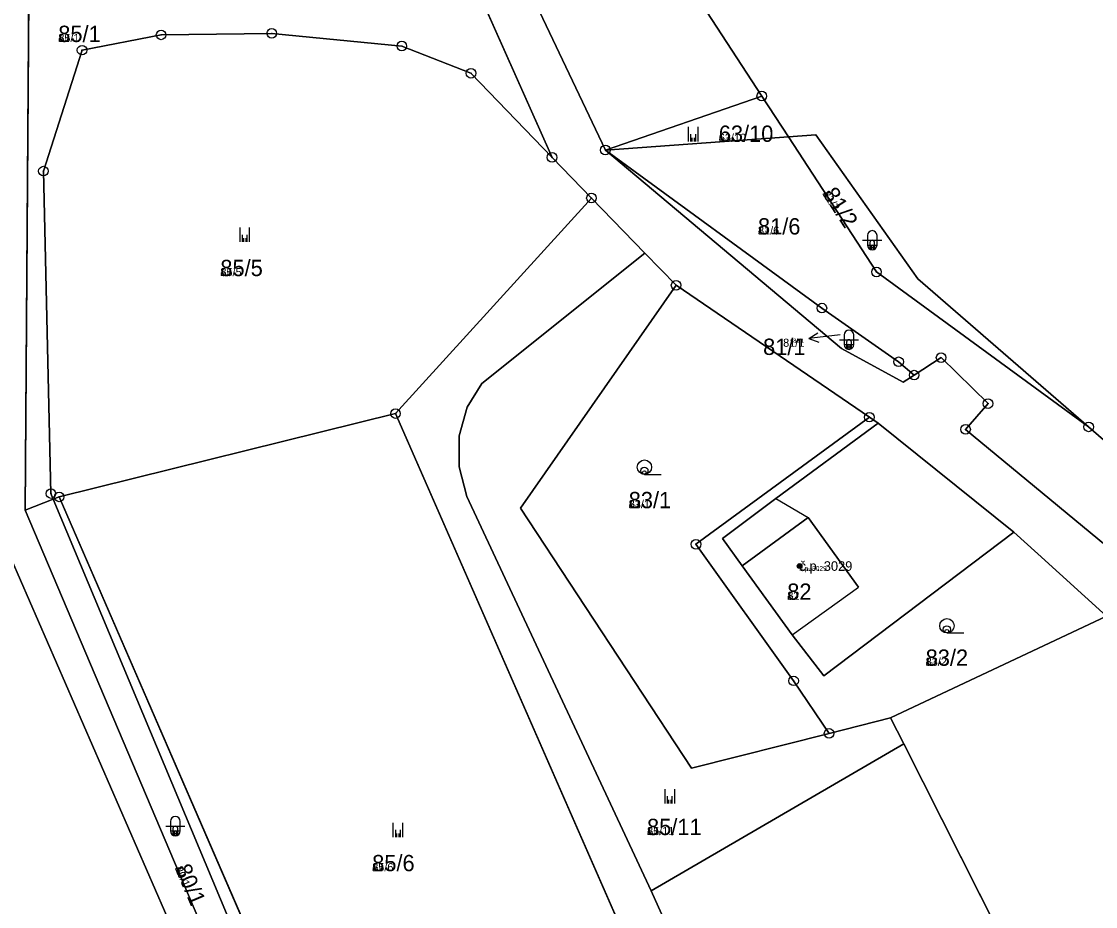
# Model space of a CAD drawing. Extents: x -759873 to -758487, y -975024 to -973516.
# Drawn here: x -759629.6 to -759517.7, y -974197.9 to -974105.6 of the extents above; entities that cross this region are included whole.
import ezdxf

# ---------------------------------------------------------------- set-up
doc = ezdxf.new("R2010")
doc.units = 0
for name, color, linetype in [('KAT_02_hranice parcel', 7, 'Continuous'), ('KAT_03_1000_st čísla parcelní', 7, 'Continuous'), ('KAT_03_1000_čísla parcelní', 7, 'Continuous'), ('KAT_03_1000_čísla popisná', 7, 'Continuous'), ('KAT_03_250_st čísla parcelní', 7, 'Continuous'), ('KAT_03_250_čísla parcelní', 7, 'Continuous'), ('KAT_03_250_čísla popisná', 7, 'Continuous'), ('KAT_03_500_st čísla parcelní', 7, 'Continuous'), ('KAT_03_500_čísla parcelní', 7, 'Continuous'), ('KAT_03_500_čísla popisná', 7, 'Continuous'), ('KAT_04_vnitřní kresba', 7, 'Continuous'), ('KAT_05_1000_značky kultur', 7, 'Continuous'), ('KAT_05_250_značky kultur', 7, 'Continuous'), ('KAT_05_500_značky kultur', 7, 'Continuous'), ('KAT_07_1000_značky budov', 7, 'Continuous'), ('KAT_07_250_značky budov', 7, 'Continuous'), ('KAT_07_500_značky budov', 7, 'Continuous'), ('KAT_11_značky bodu BP', 7, 'Continuous'), ('KAT_12_pomocná šipka', 7, 'Continuous'), ('KAT_14_plocha_budovy', 7, 'Continuous'), ('KAT_14_plocha_pozemek', 7, 'Continuous')]:
    doc.layers.add(name, color=color, linetype=linetype)

msp = doc.modelspace()

# ---------------------------------------------------------------- linework, layer by layer
at = {"layer": 'KAT_02_hranice parcel'}
for p, q in [((-759552.46, -974113.37), (-759576.5, -974076.47)), ((-759585.13, -974095.53), (-759574.33, -974119.77)), ((-759628.88, -974102.32), (-759629.25, -974156.54)), ((-759568.77, -974119), (-759552.46, -974113.37)), ((-759552.46, -974113.37), (-759549.68, -974117.63)), ((-759568.77, -974119), (-759549.68, -974117.63)), ((-759574.33, -974119.77), (-759570.22, -974124.01)), ((-759590.65, -974146.48), (-759570.22, -974124.01)), ((-759570.22, -974124.01), (-759564.64, -974129.76)), ((-759564.64, -974129.76), (-759561.39, -974133.11)), ((-759561.39, -974133.11), (-759541.24, -974146.86)), ((-759625.72, -974155.17), (-759590.65, -974146.48)), ((-759557.68, -974221.71), (-759590.65, -974146.48)), ((-759541.24, -974146.86), (-759540.34, -974147.48)), ((-759540.34, -974147.48), (-759526.16, -974158.85)), ((-759518.38, -974147.87), (-759504.51, -974159.89)), ((-759626.33, -974155.41), (-759629.25, -974156.54)), ((-759625.72, -974155.17), (-759626.33, -974155.41)), ((-759593.05, -974235), (-759626.33, -974155.41)), ((-759591.32, -974234.37), (-759625.72, -974155.17)), ((-759629.25, -974156.54), (-759595.6, -974235.94)), ((-759516.52, -974167.59), (-759539.03, -974178.21)), ((-759539.03, -974178.21), (-759545.44, -974179.83)), ((-759539.03, -974178.21), (-759537.66, -974180.93)), ((-759537.66, -974180.93), (-759563.99, -974196.25)), ((-759537.66, -974180.93), (-759523.59, -974208.74))]:
    msp.add_line(p, q, dxfattribs=at)
for points in [[(-759587.88, -974071.09), (-759581.81, -974091.52), (-759568.77, -974119)], [(-759626.33, -974155.41), (-759626.58, -974154.82), (-759627.36, -974121.2), (-759623.33, -974108.59), (-759615.09, -974107), (-759603.55, -974106.84), (-759589.99, -974108.16), (-759582.78, -974111), (-759574.33, -974119.77)], [(-759632.14, -974110.51), (-759632.59, -974157.4), (-759597.84, -974237.11), (-759593.26, -974247.61)], [(-759549.68, -974117.63), (-759546.81, -974117.43), (-759536.2, -974132.42), (-759518.38, -974147.87)], [(-759549.68, -974117.63), (-759540.5, -974131.72), (-759518.38, -974147.87)], [(-759536.57, -974142.47), (-759537.72, -974143.21), (-759544.16, -974139.71), (-759568.77, -974119)], [(-759536.57, -974142.47), (-759538.19, -974141.08), (-759546.19, -974135.48), (-759568.77, -974119)], [(-759564.64, -974129.76), (-759581.65, -974143.36), (-759583.16, -974145.82), (-759584.02, -974148.81), (-759584.01, -974152.02), (-759583.21, -974155.14), (-759563.99, -974196.25)], [(-759545.44, -974179.83), (-759559.78, -974183.44), (-759577.62, -974156.33), (-759561.39, -974133.11)], [(-759511.82, -974164.15), (-759531.21, -974148.13), (-759528.87, -974145.44), (-759533.76, -974140.65), (-759536.57, -974142.47)], [(-759545.44, -974179.83), (-759549.14, -974174.35), (-759559.32, -974160.11), (-759541.24, -974146.86)], [(-759540.34, -974147.48), (-759550.98, -974155.34), (-759556.57, -974159.52), (-759554.52, -974162.35), (-759549.3, -974169.56), (-759546, -974173.82), (-759526.16, -974158.85)], [(-759526.16, -974158.85), (-759523.66, -974161.11), (-759516.52, -974167.59)], [(-759563.99, -974196.25), (-759561.02, -974202.81), (-759558.92, -974201.9), (-759551.51, -974216.06)]]:
    msp.add_lwpolyline(points, dxfattribs=at)
at = {"layer": 'KAT_03_1000_čísla popisná'}
msp.add_circle((-759548.52, -974162.38), 0.25, dxfattribs=at)
at = {"layer": 'KAT_03_250_čísla popisná'}
msp.add_circle((-759548.52, -974162.38), 0.0625, dxfattribs=at)
at = {"layer": 'KAT_03_500_čísla popisná'}
msp.add_circle((-759548.52, -974162.38), 0.125, dxfattribs=at)
at = {"layer": 'KAT_04_vnitřní kresba'}
for p, q in [((-759550.98, -974155.34), (-759547.61, -974157.31)), ((-759554.52, -974162.35), (-759547.61, -974157.31)), ((-759547.61, -974157.31), (-759542.38, -974164.58)), ((-759549.3, -974169.56), (-759542.38, -974164.58))]:
    msp.add_line(p, q, dxfattribs=at)
at = {"layer": 'KAT_05_1000_značky kultur'}
for p, q in [((-759560.09, -974118.1), (-759560.09, -974116.6)), ((-759559.09, -974118.1), (-759559.09, -974116.6)), ((-759606.86, -974128.58), (-759606.86, -974127.08)), ((-759605.86, -974128.58), (-759605.86, -974127.08)), ((-759541.94, -974128.41), (-759539.94, -974128.41)), ((-759541.44, -974127.91), (-759541.44, -974128.91)), ((-759540.44, -974128.91), (-759540.44, -974127.91)), ((-759544.37, -974138.78), (-759542.37, -974138.78)), ((-759543.87, -974138.28), (-759543.87, -974139.28)), ((-759542.87, -974139.28), (-759542.87, -974138.28)), ((-759564.69, -974152.82), (-759562.94, -974152.82)), ((-759533.15, -974169.36), (-759531.4, -974169.36)), ((-759562.54, -974187.13), (-759562.54, -974185.63)), ((-759561.54, -974187.13), (-759561.54, -974185.63)), ((-759614.11, -974189), (-759614.11, -974190)), ((-759613.11, -974190), (-759613.11, -974189)), ((-759590.88, -974190.64), (-759590.88, -974189.14)), ((-759589.88, -974190.64), (-759589.88, -974189.14)), ((-759614.61, -974189.5), (-759612.61, -974189.5))]:
    msp.add_line(p, q, dxfattribs=at)
for centre in [(-759564.69, -974152.07), (-759533.15, -974168.61)]:
    msp.add_circle(centre, 0.75, dxfattribs=at)
for centre, start, end in [((-759540.94, -974127.91), 0, 180), ((-759540.94, -974128.91), 180, 359.9879), ((-759543.37, -974138.28), 0, 180), ((-759543.37, -974139.28), 180, 359.9879), ((-759613.61, -974189), 0, 180), ((-759613.61, -974190), 180, 359.9879)]:
    msp.add_arc(centre, 0.5, start, end, dxfattribs=at)
at = {"layer": 'KAT_05_250_značky kultur'}
for p, q in [((-759559.71, -974118.1), (-759559.71, -974117.72)), ((-759559.46, -974118.1), (-759559.46, -974117.72)), ((-759606.48, -974128.58), (-759606.48, -974128.21)), ((-759606.23, -974128.58), (-759606.23, -974128.21)), ((-759541.19, -974129.16), (-759540.69, -974129.16)), ((-759541.07, -974129.04), (-759541.07, -974129.29)), ((-759540.81, -974129.29), (-759540.81, -974129.04)), ((-759543.62, -974139.53), (-759543.12, -974139.53)), ((-759543.5, -974139.41), (-759543.5, -974139.66)), ((-759543.24, -974139.66), (-759543.24, -974139.41)), ((-759564.7, -974152.82), (-759564.26, -974152.82)), ((-759533.16, -974169.36), (-759532.72, -974169.36)), ((-759562.16, -974187.13), (-759562.16, -974186.76)), ((-759561.91, -974187.13), (-759561.91, -974186.76)), ((-759613.86, -974190.25), (-759613.36, -974190.25)), ((-759613.74, -974190.13), (-759613.74, -974190.38)), ((-759613.48, -974190.38), (-759613.48, -974190.13)), ((-759590.5, -974190.64), (-759590.5, -974190.27)), ((-759590.25, -974190.64), (-759590.25, -974190.27))]:
    msp.add_line(p, q, dxfattribs=at)
for centre in [(-759564.7, -974152.63), (-759533.16, -974169.17)]:
    msp.add_circle(centre, 0.187, dxfattribs=at)
for centre, start, end in [((-759540.94, -974129.04), 0, 180), ((-759540.94, -974129.29), 180, 359.9879), ((-759543.37, -974139.41), 0, 180), ((-759543.37, -974139.66), 180, 359.9879), ((-759613.61, -974190.13), 0, 180), ((-759613.61, -974190.38), 180, 359.9879)]:
    msp.add_arc(centre, 0.125, start, end, dxfattribs=at)
at = {"layer": 'KAT_05_500_značky kultur'}
for p, q in [((-759559.84, -974118.1), (-759559.84, -974117.35)), ((-759559.33, -974118.1), (-759559.33, -974117.35)), ((-759606.61, -974128.58), (-759606.61, -974127.83)), ((-759606.1, -974128.58), (-759606.1, -974127.83)), ((-759541.19, -974128.66), (-759541.19, -974129.16)), ((-759540.69, -974129.16), (-759540.69, -974128.66)), ((-759541.44, -974128.91), (-759540.44, -974128.91)), ((-759543.87, -974139.28), (-759542.87, -974139.28)), ((-759543.62, -974139.03), (-759543.62, -974139.53)), ((-759543.12, -974139.53), (-759543.12, -974139.03)), ((-759564.7, -974152.82), (-759563.82, -974152.82)), ((-759533.16, -974169.36), (-759532.28, -974169.36)), ((-759562.29, -974187.13), (-759562.29, -974186.38)), ((-759561.79, -974187.13), (-759561.79, -974186.38)), ((-759614.11, -974190), (-759613.11, -974190)), ((-759613.86, -974189.75), (-759613.86, -974190.25)), ((-759613.36, -974190.25), (-759613.36, -974189.75)), ((-759590.63, -974190.64), (-759590.63, -974189.89)), ((-759590.12, -974190.64), (-759590.12, -974189.89))]:
    msp.add_line(p, q, dxfattribs=at)
for centre in [(-759564.7, -974152.44), (-759533.16, -974168.98)]:
    msp.add_circle(centre, 0.375, dxfattribs=at)
for centre, start, end in [((-759540.94, -974128.66), 0, 180), ((-759540.94, -974129.16), 180, 359.9879), ((-759543.37, -974139.03), 0, 180), ((-759543.37, -974139.53), 180, 359.9879), ((-759613.61, -974189.75), 0, 180), ((-759613.61, -974190.25), 180, 359.9879)]:
    msp.add_arc(centre, 0.25, start, end, dxfattribs=at)
at = {"layer": 'KAT_07_1000_značky budov'}
msp.add_circle((-759548.53, -974162.38), 0.175, dxfattribs=at)
at = {"layer": 'KAT_07_250_značky budov'}
msp.add_circle((-759548.52, -974162.38), 0.0437, dxfattribs=at)
at = {"layer": 'KAT_07_500_značky budov'}
msp.add_circle((-759548.52, -974162.38), 0.0875, dxfattribs=at)
at = {"layer": 'KAT_11_značky bodu BP'}
for centre, radius in [((-759603.55, -974106.84), 0.5), ((-759615.09, -974107), 0.5), ((-759615.09, -974107), 0.0303), ((-759603.55, -974106.84), 0.0303), ((-759623.33, -974108.59), 0.5), ((-759623.33, -974108.59), 0.0303), ((-759589.99, -974108.16), 0.5), ((-759589.99, -974108.16), 0.0303), ((-759582.78, -974111), 0.5), ((-759582.78, -974111), 0.0303), ((-759552.46, -974113.37), 0.5), ((-759552.46, -974113.37), 0.0303), ((-759568.77, -974119), 0.5), ((-759574.33, -974119.77), 0.5), ((-759574.33, -974119.77), 0.0303), ((-759568.77, -974119), 0.0303), ((-759627.36, -974121.2), 0.5), ((-759627.36, -974121.2), 0.0303), ((-759570.22, -974124.01), 0.5), ((-759570.22, -974124.01), 0.0303), ((-759540.5, -974131.72), 0.5), ((-759540.5, -974131.72), 0.0303), ((-759561.39, -974133.11), 0.5), ((-759561.39, -974133.11), 0.0303), ((-759546.19, -974135.48), 0.5), ((-759546.19, -974135.48), 0.0303), ((-759538.19, -974141.08), 0.5), ((-759538.19, -974141.08), 0.0303), ((-759533.76, -974140.65), 0.5), ((-759533.76, -974140.65), 0.0303), ((-759536.57, -974142.47), 0.5), ((-759536.57, -974142.47), 0.0303), ((-759528.87, -974145.44), 0.5), ((-759528.87, -974145.44), 0.0303), ((-759590.65, -974146.48), 0.5), ((-759590.65, -974146.48), 0.0303), ((-759541.24, -974146.86), 0.5), ((-759541.24, -974146.86), 0.0303), ((-759531.21, -974148.13), 0.5), ((-759518.38, -974147.87), 0.5), ((-759518.38, -974147.87), 0.0303), ((-759531.21, -974148.13), 0.0303), ((-759626.58, -974154.82), 0.5), ((-759626.58, -974154.82), 0.0303), ((-759625.72, -974155.17), 0.5), ((-759625.72, -974155.17), 0.0303), ((-759559.32, -974160.11), 0.5), ((-759559.32, -974160.11), 0.0303), ((-759549.14, -974174.35), 0.5), ((-759549.14, -974174.35), 0.0303), ((-759545.44, -974179.83), 0.5), ((-759545.44, -974179.83), 0.0303)]:
    msp.add_circle(centre, radius, dxfattribs=at)
at = {"layer": 'KAT_12_pomocná šipka'}
for p, q in [((-759547.56, -974138.67), (-759546.63, -974138.05)), ((-759544.58, -974138.3), (-759547.56, -974138.67)), ((-759547.56, -974138.67), (-759546.5, -974139.04)), ((-759544.28, -974138.26), (-759544.58, -974138.3))]:
    msp.add_line(p, q, dxfattribs=at)
at = {"layer": 'KAT_14_plocha_budovy'}
msp.add_lwpolyline([(-759554.52, -974162.35), (-759549.3, -974169.56), (-759542.38, -974164.58), (-759547.61, -974157.31)], close=True, dxfattribs=at)
at = {"layer": 'KAT_14_plocha_pozemek'}
for points in [[(-759593.11, -974016.5), (-759592.85, -974058.75), (-759592.59, -974066.4), (-759592.39, -974072.39), (-759589.64, -974081.94), (-759586.56, -974092.63), (-759585.13, -974095.53), (-759574.33, -974119.77), (-759570.22, -974124.01), (-759564.64, -974129.76), (-759561.39, -974133.11), (-759541.24, -974146.86), (-759540.34, -974147.48), (-759526.16, -974158.85), (-759523.66, -974161.11), (-759516.52, -974167.59), (-759486.83, -974191.58), (-759468.95, -974205.58), (-759465.22, -974208.76), (-759464.16, -974209.67), (-759453.16, -974219.06), (-759423.45, -974241.84)], [(-759428.19, -974233.35), (-759448.25, -974217.2), (-759461.7, -974206.38), (-759466.62, -974201.75), (-759468.82, -974199.68), (-759511.82, -974164.15), (-759531.21, -974148.13), (-759528.87, -974145.44), (-759533.76, -974140.65), (-759536.57, -974142.47), (-759537.72, -974143.21), (-759544.16, -974139.71), (-759568.77, -974119), (-759581.81, -974091.52), (-759587.88, -974071.09), (-759587.42, -974054.22), (-759584.71, -974017.13)], [(-759572.7, -974036.6), (-759569.19, -974051.29), (-759567.32, -974066.36), (-759576.5, -974076.47), (-759552.46, -974113.37), (-759549.68, -974117.63), (-759546.81, -974117.43), (-759536.2, -974132.42), (-759518.38, -974147.87), (-759504.51, -974159.89), (-759486.63, -974175.39), (-759468.43, -974180.91), (-759467.07, -974178.39), (-759455.27, -974173.93), (-759439.19, -974173.13), (-759427.95, -974173.9)], [(-759577.29, -974280.17), (-759595.44, -974248.79), (-759593.26, -974247.61), (-759597.84, -974237.11), (-759632.59, -974157.4), (-759632.14, -974110.51), (-759643.4, -974116.83), (-759682.64, -974128.82), (-759683.76, -974126.26), (-759645.25, -974113.94), (-759633.6, -974107.37), (-759632.1, -974106.83), (-759632.05, -974101.17), (-759670.93, -974083.68), (-759719.88, -974055.79)], [(-759567.96, -974276.65), (-759571.75, -974271.74), (-759578.95, -974260.75), (-759586.25, -974249.97), (-759595.6, -974235.94), (-759629.25, -974156.54), (-759628.88, -974102.32), (-759632.05, -974101.17), (-759632.1, -974106.83), (-759632.14, -974110.51), (-759632.59, -974157.4), (-759597.84, -974237.11), (-759593.26, -974247.61), (-759569.36, -974281.77)]]:
    msp.add_lwpolyline(points, dxfattribs=at)
for points in [[(-759552.46, -974113.37), (-759576.5, -974076.47), (-759577.62, -974077.7), (-759587.88, -974071.09), (-759581.81, -974091.52), (-759568.77, -974119)], [(-759623.33, -974108.59), (-759615.09, -974107), (-759603.55, -974106.84), (-759589.99, -974108.16), (-759582.78, -974111), (-759574.33, -974119.77), (-759585.13, -974095.53), (-759595.87, -974097.2), (-759587.39, -974104.75), (-759602.93, -974103.62), (-759615.11, -974103.47), (-759621.09, -974101.11), (-759628.88, -974102.32), (-759629.25, -974156.54), (-759626.33, -974155.41), (-759626.58, -974154.82), (-759627.36, -974121.2)], [(-759590.65, -974146.48), (-759570.22, -974124.01), (-759574.33, -974119.77), (-759582.78, -974111), (-759589.99, -974108.16), (-759603.55, -974106.84), (-759615.09, -974107), (-759623.33, -974108.59), (-759627.36, -974121.2), (-759626.58, -974154.82), (-759626.33, -974155.41), (-759625.72, -974155.17)], [(-759549.68, -974117.63), (-759552.46, -974113.37), (-759568.77, -974119)], [(-759504.51, -974159.89), (-759518.38, -974147.87), (-759540.5, -974131.72), (-759549.68, -974117.63), (-759568.77, -974119), (-759546.19, -974135.48), (-759538.19, -974141.08), (-759536.57, -974142.47), (-759533.76, -974140.65), (-759528.87, -974145.44), (-759531.21, -974148.13), (-759511.82, -974164.15)], [(-759518.38, -974147.87), (-759536.2, -974132.42), (-759546.81, -974117.43), (-759549.68, -974117.63), (-759540.5, -974131.72)], [(-759538.19, -974141.08), (-759546.19, -974135.48), (-759568.77, -974119), (-759544.16, -974139.71), (-759537.72, -974143.21), (-759536.57, -974142.47)], [(-759570.22, -974124.01), (-759590.65, -974146.48), (-759557.68, -974221.71), (-759552.51, -974219.77), (-759550.04, -974218.83), (-759551.51, -974216.06), (-759558.92, -974201.9), (-759561.02, -974202.81), (-759563.99, -974196.25), (-759583.21, -974155.14), (-759584.01, -974152.02), (-759584.02, -974148.81), (-759583.16, -974145.82), (-759581.65, -974143.36), (-759564.64, -974129.76)], [(-759545.44, -974179.83), (-759559.78, -974183.44), (-759577.62, -974156.33), (-759561.39, -974133.11), (-759564.64, -974129.76), (-759581.65, -974143.36), (-759583.16, -974145.82), (-759584.02, -974148.81), (-759584.01, -974152.02), (-759583.21, -974155.14), (-759563.99, -974196.25), (-759537.66, -974180.93), (-759539.03, -974178.21)], [(-759549.14, -974174.35), (-759559.32, -974160.11), (-759541.24, -974146.86), (-759561.39, -974133.11), (-759577.62, -974156.33), (-759559.78, -974183.44), (-759545.44, -974179.83)], [(-759557.68, -974221.71), (-759590.65, -974146.48), (-759625.72, -974155.17), (-759591.32, -974234.37)], [(-759541.24, -974146.86), (-759559.32, -974160.11), (-759549.14, -974174.35), (-759545.44, -974179.83), (-759539.03, -974178.21), (-759516.52, -974167.59), (-759523.66, -974161.11), (-759526.16, -974158.85), (-759546, -974173.82), (-759549.3, -974169.56), (-759554.52, -974162.35), (-759556.57, -974159.52), (-759550.98, -974155.34), (-759540.34, -974147.48)], [(-759540.34, -974147.48), (-759550.98, -974155.34), (-759556.57, -974159.52), (-759554.52, -974162.35), (-759549.3, -974169.56), (-759546, -974173.82), (-759526.16, -974158.85)], [(-759593.05, -974235), (-759626.33, -974155.41), (-759629.25, -974156.54), (-759595.6, -974235.94)], [(-759591.32, -974234.37), (-759625.72, -974155.17), (-759626.33, -974155.41), (-759593.05, -974235)], [(-759537.66, -974180.93), (-759523.59, -974208.74), (-759515.75, -974205.6), (-759504.06, -974200.98), (-759489.51, -974195.05), (-759486.83, -974191.58), (-759516.52, -974167.59), (-759539.03, -974178.21)], [(-759561.02, -974202.81), (-759558.92, -974201.9), (-759551.51, -974216.06), (-759536.51, -974210.36), (-759535.23, -974213.18), (-759523.59, -974208.74), (-759537.66, -974180.93), (-759563.99, -974196.25)]]:
    msp.add_lwpolyline(points, close=True, dxfattribs=at)

# ---------------------------------------------------------------- texts
at = {"layer": 'KAT_03_1000_st čísla parcelní'}
msp.add_text('82', height=1.7, dxfattribs=at).set_placement((-759549.8, -974165.9))
at = {"layer": 'KAT_03_1000_čísla parcelní'}
for s, p in [('85/1', (-759625.81, -974107.74)), ('63/10', (-759556.94, -974118.15)), ('81/6', (-759552.85, -974127.81)), ('85/5', (-759608.91, -974132.15)), ('81/1', (-759552.32, -974140.37)), ('83/1', (-759566.33, -974156.35)), ('83/2', (-759535.37, -974172.78)), ('85/11', (-759564.42, -974190.43)), ('85/6', (-759593.08, -974194.2))]:
    msp.add_text(s, height=1.7, dxfattribs=at).set_placement(p)
for s, rotation, p in [('81/2', 303, (-759546.17, -974123.58)), ('80/1', 293, (-759613.67, -974193.88))]:
    msp.add_text(s, height=1.7, rotation=rotation, dxfattribs=at).set_placement(p)
at = {"layer": 'KAT_03_1000_čísla popisná'}
msp.add_text('č.p. 3029', height=1, dxfattribs=at).set_placement((-759548.52, -974162.88))
at = {"layer": 'KAT_03_250_st čísla parcelní'}
msp.add_text('82', height=0.425, dxfattribs=at).set_placement((-759549.8, -974165.9))
at = {"layer": 'KAT_03_250_čísla parcelní'}
for s, p in [('85/1', (-759625.81, -974107.74)), ('63/10', (-759556.94, -974118.15)), ('81/6', (-759552.85, -974127.81)), ('85/5', (-759608.91, -974132.15)), ('81/1', (-759549.18, -974139.1)), ('83/1', (-759566.33, -974156.35)), ('83/2', (-759535.37, -974172.78)), ('85/11', (-759564.42, -974190.43)), ('85/6', (-759593.08, -974194.2))]:
    msp.add_text(s, height=0.425, dxfattribs=at).set_placement(p)
for s, rotation, p in [('81/2', 303, (-759546.17, -974123.58)), ('80/1', 293, (-759613.67, -974193.88))]:
    msp.add_text(s, height=0.425, rotation=rotation, dxfattribs=at).set_placement(p)
at = {"layer": 'KAT_03_250_čísla popisná'}
msp.add_text('č.p. 3029', height=0.25, dxfattribs=at).set_placement((-759548.52, -974162.88))
at = {"layer": 'KAT_03_500_st čísla parcelní'}
msp.add_text('82', height=0.85, dxfattribs=at).set_placement((-759549.8, -974165.9))
at = {"layer": 'KAT_03_500_čísla parcelní'}
for s, p in [('85/1', (-759625.81, -974107.74)), ('63/10', (-759556.94, -974118.15)), ('81/6', (-759552.85, -974127.81)), ('85/5', (-759608.91, -974132.15)), ('81/1', (-759550.23, -974139.52)), ('83/1', (-759566.33, -974156.35)), ('83/2', (-759535.37, -974172.78)), ('85/11', (-759564.42, -974190.43)), ('85/6', (-759593.08, -974194.2))]:
    msp.add_text(s, height=0.85, dxfattribs=at).set_placement(p)
for s, rotation, p in [('81/2', 303, (-759546.17, -974123.58)), ('80/1', 293, (-759613.67, -974193.88))]:
    msp.add_text(s, height=0.85, rotation=rotation, dxfattribs=at).set_placement(p)
at = {"layer": 'KAT_03_500_čísla popisná'}
msp.add_text('č.p. 3029', height=0.5, dxfattribs=at).set_placement((-759548.52, -974162.88))

doc.saveas('drawing.dxf')
